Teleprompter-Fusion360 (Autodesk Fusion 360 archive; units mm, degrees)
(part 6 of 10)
sketch "Skizze70" plane through (0, 0, 150.455) normal (0, 0, 1) x axis (-1, 0, 0)
  line L1 (-222.0031, -133.7) -> (-201.1146, -176.9513)
  line L2 (-272.0031, -133.7) -> (-222.0031, -133.7)
  line L3 (-225.1361, -216.1858) -> (-272.0031, -133.7)
  line L4 (-222.0031, -323.7) -> (-222.0031, -228.0421)
  line L5 (-137.0031, -323.7) -> (-222.0031, -323.7)
  line L6 (-137.0031, -228.0421) -> (-137.0031, -323.7)
  line L7 (-87.0031, -133.7) -> (-133.87, -216.1858)
  line L8 (-137.0031, -133.7) -> (-87.0031, -133.7)
  line L9 (-157.8915, -176.9513) -> (-137.0031, -133.7)
  line L10 (-179.5031, -166.5139) -> (-179.5031, -323.7)
  arc A1 centre (-179.5031, -166.5139) radius 24 clockwise from (-157.8915, -176.9513) to (-201.1146, -176.9513)
  arc A2 centre (-246.0031, -228.0421) radius 24 clockwise from (-225.1361, -216.1858) to (-222.0031, -228.0421)
  arc A3 centre (-113.0031, -228.0421) radius 24 clockwise from (-137.0031, -228.0421) to (-133.87, -216.1858)
  circle C1 centre (-179.5031, -203.0903) radius 3.25
  circle C2 centre (-179.5031, -215.0903) radius 3.25
  circle C3 centre (-179.5031, -227.0903) radius 3.25
  circle C4 centre (-179.5031, -239.0903) radius 3.25
  circle C5 centre (-179.5031, -251.0903) radius 3.25
  circle C6 centre (-179.5031, -263.0903) radius 3.25
  circle C7 centre (-179.5031, -275.0903) radius 3.25
  circle C8 centre (-179.5031, -287.0903) radius 3.25
  circle C9 centre (-179.5031, -299.0903) radius 3.25
  point P17 (-179.5031, -323.7)
  point P4 (-179.5031, -166.5139)
  point P18 (-179.5031, -166.5139)
  point P19 (-179.5031, -203.0903)
  midpoint L5 P17
  coincident P4 P18
  coincident L10 P19
  dimension "d401" diameter C1 = 6.5
  dimension "d404" R-Pattern1-uDistance = -12
  dimension "d405" R-Pattern1-vDistance = 0
extrude "Extrusion71" cut sketch "Skizze70" profile of C1 C2 C3 C4 C5 C6 C7 C8 C9 against normal blind 20
extrude "Extrusion72" cut of existing geometry to an object
sketch "Skizze71" plane through (0, 0, 138.455) normal (0, 0, -1) x axis (1, 0, 0)
  line L1 (137.0031, -133.7) -> (157.8915, -176.9513)
  line L2 (87.0031, -133.7) -> (137.0031, -133.7)
  line L3 (133.87, -216.1858) -> (87.0031, -133.7)
  line L4 (137.0031, -323.7) -> (137.0031, -228.0421)
  line L5 (222.0031, -323.7) -> (137.0031, -323.7)
  line L6 (222.0031, -228.0421) -> (222.0031, -323.7)
  line L7 (272.0031, -133.7) -> (225.1361, -216.1858)
  line L8 (222.0031, -133.7) -> (272.0031, -133.7)
  line L9 (201.1146, -176.9513) -> (222.0031, -133.7)
  line L10 (164.5031, -299.0903) -> (164.5031, -203.0903)
  line L11 (194.5031, -203.0903) -> (194.5031, -299.0903)
  line L12 (179.5031, -299.0903) -> (179.5031, -203.0903)
  line L13 (137.0031, -311.6994) -> (222.0031, -311.6994)
  circle C1 centre (179.5031, -275.0903) radius 3.25
  circle C2 centre (179.5031, -227.0903) radius 3.25
  circle C3 centre (179.5031, -215.0903) radius 3.25
  circle C4 centre (179.5031, -263.0903) radius 3.25
  circle C5 centre (179.5031, -287.0903) radius 3.25
  circle C6 centre (179.5031, -239.0903) radius 3.25
  circle C7 centre (179.5031, -203.0903) radius 3.25
  circle C8 centre (179.5031, -251.0903) radius 3.25
  circle C9 centre (179.5031, -299.0903) radius 3.25
  arc A1 centre (113.0031, -228.0421) radius 24 clockwise from (133.87, -216.1858) to (137.0031, -228.0421)
  arc A2 centre (246.0031, -228.0421) radius 24 clockwise from (222.0031, -228.0421) to (225.1361, -216.1858)
  arc A3 centre (179.5031, -166.5139) radius 24 clockwise from (201.1146, -176.9513) to (157.8915, -176.9513)
  arc A4 centre (179.5031, -299.0903) radius 15 clockwise from (194.5031, -299.0903) to (164.5031, -299.0903)
  arc A5 centre (179.5031, -203.0903) radius 15 clockwise from (164.5031, -203.0903) to (194.5031, -203.0903)
  point P10 (179.5031, -299.0903)
  point P31 (179.5031, -299.0903)
  point P8 (179.5031, -203.0903)
  point P30 (179.5031, -203.0903)
  tangent L10 A4
  tangent A4 L11
  parallel L10 L11
  tangent L11 A5
  tangent L10 A5
  coincident P10 P31
  vertical L12
  coincident P8 P30
  dimension "d410" diameter A4 = 30
extrude "Extrusion73" cut sketch "Skizze71" profile of C1 C2 C3 C4 C5 C6 C7 C8 C9 A3 L10 A4 L11 A5 L13 against normal blind 8
sketch "Skizze72" plane through (0, 323.7, 0) normal (0, 1, 0) x axis (-1, 0, 0)
  line L1 (-137.0031, 0) -> (-222.0031, 0)
  line L2 (-137.0031, 138.455) -> (-137.0031, 0)
  line L3 (-222.0031, 138.455) -> (-137.0031, 138.455)
  line L4 (-222.0031, 0) -> (-222.0031, 138.455)
  line L5 (-137.0031, 150.455) -> (-137.0031, 138.455)
  line L6 (-222.0031, 150.455) -> (-137.0031, 150.455)
  line L7 (-222.0031, 138.455) -> (-222.0031, 150.455)
  line L8 (-137.0031, 138.455) -> (-222.0031, 138.455)
  line L9 (-154.0031, 138.455) -> (-154.0031, 150.455)
  line L10 (-171.0031, 138.455) -> (-171.0031, 150.455)
  line L11 (-188.0031, 138.455) -> (-188.0031, 150.455)
  line L12 (-205.0031, 138.455) -> (-205.0031, 150.455)
  point P10 (-154.0031, 150.455)
  point P11 (-154.0031, 138.455)
  point P12 (-171.0031, 150.455)
  point P13 (-171.0031, 138.455)
  point P14 (-188.0031, 150.455)
  point P15 (-188.0031, 138.455)
  point P16 (-205.0031, 150.455)
  point P17 (-205.0031, 138.455)
  coincident L6 P10
  coincident L8 P11
  perpendicular L8 L9
  coincident L6 P12
  coincident L8 P13
  perpendicular L8 L10
  coincident L6 P14
  coincident L3 P15
  perpendicular L3 L11
  coincident L6 P16
  coincident L8 P17
  perpendicular L8 L12
  dimension "d413" distance L5 L7 = 85
  dimension "d414" distance L5 L9 = 17 (= "85.00 mm / 5")
  dimension "d415" distance L9 L10 = 17 (= "d414")
  dimension "d416" distance L10 L11 = 17 (= "d414")
  dimension "d417" distance L11 L12 = 17 (= "d414")
extrude "Extrusion74" add sketch "Skizze72" profile of L3 L6 L8 L9 L10 L11 L12 against normal blind 12
sketch "Skizze73" plane through (0, 0, 150.455) normal (0, 0, 1) x axis (-1, 0, 0)
  line L1 (-222.0031, -133.7) -> (-201.1146, -176.9513)
  line L2 (-272.0031, -133.7) -> (-222.0031, -133.7)
  line L3 (-225.1361, -216.1858) -> (-272.0031, -133.7)
  line L4 (-222.0031, -323.7) -> (-222.0031, -228.0421)
  line L5 (-137.0031, -323.7) -> (-222.0031, -323.7)
  line L6 (-137.0031, -228.0421) -> (-137.0031, -323.7)
  line L7 (-87.0031, -133.7) -> (-133.87, -216.1858)
  line L8 (-137.0031, -133.7) -> (-87.0031, -133.7)
  line L9 (-157.8915, -176.9513) -> (-137.0031, -133.7)
  line L10 (-154.0031, -323.7) -> (-171.0031, -323.7)
  line L11 (-154.0031, -311.7) -> (-154.0031, -323.7)
  line L12 (-171.0031, -311.7) -> (-154.0031, -311.7)
  line L13 (-171.0031, -323.7) -> (-171.0031, -311.7)
  line L14 (-188.0031, -323.7) -> (-205.0031, -323.7)
  line L15 (-188.0031, -311.7) -> (-188.0031, -323.7)
  line L16 (-205.0031, -311.7) -> (-188.0031, -311.7)
  line L17 (-205.0031, -323.7) -> (-205.0031, -311.7)
  circle C1 centre (-179.5031, -275.0903) radius 3.25
  circle C2 centre (-179.5031, -227.0903) radius 3.25
  circle C3 centre (-179.5031, -215.0903) radius 3.25
  circle C4 centre (-179.5031, -263.0903) radius 3.25
  circle C5 centre (-179.5031, -287.0903) radius 3.25
  circle C6 centre (-179.5031, -239.0903) radius 3.25
  circle C7 centre (-179.5031, -203.0903) radius 3.25
  circle C8 centre (-179.5031, -251.0903) radius 3.25
  circle C9 centre (-179.5031, -299.0903) radius 3.25
  arc A1 centre (-179.5031, -166.5139) radius 24 clockwise from (-157.8915, -176.9513) to (-201.1146, -176.9513)
  arc A2 centre (-246.0031, -228.0421) radius 24 clockwise from (-225.1361, -216.1858) to (-222.0031, -228.0421)
  arc A3 centre (-113.0031, -228.0421) radius 24 clockwise from (-137.0031, -228.0421) to (-133.87, -216.1858)
extrude "Extrusion75" cut sketch "Skizze73" profile of L5 L10 L11 L12 L13 L14 L15 L16 L17 against normal blind 15
sketch "Skizze74" plane through (0, 0, 12) normal (0, 0, 1) x axis (-1, 0, 0)
  line L1 (-374.0031, -240.1877) -> (-366.2457, -240.1877)
  line L2 (-374.0031, -255.3404) -> (-374.0031, -240.1877)
  line L3 (-246.0031, -255.3404) -> (-374.0031, -255.3404)
  line L4 (-222.0031, -311.6994) -> (-222.0031, -279.3404)
  line L5 (-137.0031, -279.3404) -> (-137.0031, -311.6994)
  line L6 (14.9969, -255.3404) -> (-113.0031, -255.3404)
  line L7 (14.9969, -240.1877) -> (14.9969, -255.3404)
  line L8 (7.2396, -240.1877) -> (14.9969, -240.1877)
  line L9 (-362.0031, -240.1877) -> (2.9969, -240.1877)
  line L10 (-171.0031, -311.7) -> (-171.0031, -323.7)
  line L11 (-154.0031, -311.7) -> (-171.0031, -311.7)
  line L12 (-154.0031, -323.7) -> (-154.0031, -311.7)
  line L13 (-137.0031, -323.7) -> (-154.0031, -323.7)
  line L14 (-137.0031, -228.0421) -> (-137.0031, -323.7)
  line L15 (-87.0031, -133.7) -> (-133.87, -216.1858)
  line L16 (-137.0031, -133.7) -> (-87.0031, -133.7)
  line L17 (-157.8915, -176.9513) -> (-137.0031, -133.7)
  line L18 (-222.0031, -133.7) -> (-201.1146, -176.9513)
  line L19 (-272.0031, -133.7) -> (-222.0031, -133.7)
  line L20 (-225.1361, -216.1858) -> (-272.0031, -133.7)
  line L21 (-222.0031, -323.7) -> (-222.0031, -228.0421)
  line L22 (-205.0031, -323.7) -> (-222.0031, -323.7)
  line L23 (-205.0031, -311.7) -> (-205.0031, -323.7)
  line L24 (-188.0031, -311.7) -> (-205.0031, -311.7)
  line L25 (-188.0031, -323.7) -> (-188.0031, -311.7)
  line L26 (-171.0031, -323.7) -> (-188.0031, -323.7)
  circle C1 centre (8.9969, -246.1877) radius 1.5
  circle C2 centre (-368.0031, -246.1877) radius 1.5
  arc A1 centre (-364.1244, -238.0664) radius 3 clockwise from (-362.0031, -240.1877) to (-366.2457, -240.1877)
  arc A2 centre (-246.0031, -279.3404) radius 24 clockwise from (-246.0031, -255.3404) to (-222.0031, -279.3404)
  arc A3 centre (-113.0031, -279.3404) radius 24 clockwise from (-137.0031, -279.3404) to (-113.0031, -255.3404)
  arc A4 centre (5.1183, -238.0664) radius 3 clockwise from (7.2396, -240.1877) to (2.9969, -240.1877)
  arc A5 centre (-113.0031, -228.0421) radius 24 clockwise from (-137.0031, -228.0421) to (-133.87, -216.1858)
  arc A6 centre (-179.5031, -166.5139) radius 24 clockwise from (-157.8915, -176.9513) to (-201.1146, -176.9513)
  arc A7 centre (-246.0031, -228.0421) radius 24 clockwise from (-225.1361, -216.1858) to (-222.0031, -228.0421)
  circle C3 centre (-179.5031, -299.0903) radius 3.25
  circle C4 centre (-179.5031, -251.0903) radius 3.25
  circle C5 centre (-179.5031, -203.0903) radius 3.25
  circle C6 centre (-179.5031, -239.0903) radius 3.25
  circle C7 centre (-179.5031, -287.0903) radius 3.25
  circle C8 centre (-179.5031, -263.0903) radius 3.25
  circle C9 centre (-179.5031, -215.0903) radius 3.25
  circle C10 centre (-179.5031, -227.0903) radius 3.25
  circle C11 centre (-179.5031, -275.0903) radius 3.25
extrude "Extrusion76" add sketch "Skizze74" profile of L4 L5 L9 L10 L11 L12 L13 L14 L21 L22 L23 L24 L25 L26 C3 C4 C6 C7 C8 C11 against normal blind 12
sketch "Skizze76" plane through (0, 133.7, 0) normal (0, -1, 0) x axis (1, 0, 0)
  line L1 (272.0031, 150.455) -> (272.0031, 138.455)
  line L2 (222.0031, 150.455) -> (272.0031, 150.455)
  line L3 (222.0031, 138.455) -> (222.0031, 150.455)
  line L4 (272.0031, 138.455) -> (222.0031, 138.455)
  line L5 (247.0031, 138.455) -> (247.0031, 150.455)
  point P6 (247.0031, 150.455)
  point P7 (247.0031, 138.455)
  midpoint L2 P6
  midpoint L4 P7
extrude "Extrusion77" cut sketch "Skizze76" profile of L1 L2 L4 L5 along normal blind 12
sketch "Skizze77" plane through (0, 133.7, 0) normal (0, -1, 0) x axis (1, 0, 0)
  line L1 (272.0031, 150.455) -> (272.0031, 138.455)
  line L2 (222.0031, 150.455) -> (272.0031, 150.455)
  line L3 (222.0031, 138.455) -> (222.0031, 150.455)
  line L4 (272.0031, 138.455) -> (222.0031, 138.455)
  line L5 (247.0031, 150.455) -> (247.0031, 138.455)
  line L6 (272.0031, 150.455) -> (247.0031, 150.455)
  line L7 (272.0031, 232.955) -> (272.0031, 150.455)
  line L8 (111.0031, 256.955) -> (248.0031, 256.955)
  line L9 (87.0031, 138.455) -> (87.0031, 232.955)
  line L10 (137.0031, 138.455) -> (87.0031, 138.455)
  line L11 (137.0031, 202.455) -> (137.0031, 138.455)
  line L12 (192.0031, 232.455) -> (167.0031, 232.455)
  line L13 (222.0031, 138.455) -> (222.0031, 202.455)
  line L14 (247.0031, 138.455) -> (222.0031, 138.455)
  circle C1 centre (112.0031, 191.955) radius 2
  circle C2 centre (112.0031, 231.955) radius 2
  circle C3 centre (247.0031, 231.955) radius 2
  circle C4 centre (247.0031, 191.955) radius 2
  arc A1 centre (248.0031, 232.955) radius 24 clockwise from (248.0031, 256.955) to (272.0031, 232.955)
  arc A2 centre (111.0031, 232.955) radius 24 clockwise from (87.0031, 232.955) to (111.0031, 256.955)
  arc A3 centre (167.0031, 202.455) radius 30 clockwise from (137.0031, 202.455) to (167.0031, 232.455)
  arc A4 centre (192.0031, 202.455) radius 30 clockwise from (192.0031, 232.455) to (222.0031, 202.455)
extrude "Extrusion78" add sketch "Skizze77" profile of L1 L2 L4 L5 L6 along normal blind 12
sketch "Skizze78" plane through (0, 121.7, 0) normal (0, -1, 0) x axis (1, 0, 0)
  line L1 (247.0031, 150.455) -> (247.0031, 138.455)
  line L2 (272.0031, 150.455) -> (247.0031, 150.455)
  line L3 (272.0031, 232.955) -> (272.0031, 150.455)
  line L4 (111.0031, 256.955) -> (248.0031, 256.955)
  line L5 (87.0031, 138.455) -> (87.0031, 232.955)
  line L6 (137.0031, 138.455) -> (87.0031, 138.455)
  line L7 (137.0031, 202.455) -> (137.0031, 138.455)
  line L8 (192.0031, 232.455) -> (167.0031, 232.455)
  line L9 (222.0031, 138.455) -> (222.0031, 202.455)
  line L10 (247.0031, 138.455) -> (222.0031, 138.455)
  line L11 (137.0031, 163.3013) -> (137.0031, 150.455)
  line L12 (137.0031, 202.455) -> (137.0031, 189.1087)
  line L13 (192.0031, 232.455) -> (167.0031, 232.455)
  line L14 (222.0031, 189.1083) -> (222.0031, 202.455)
  line L15 (222.0031, 150.455) -> (222.0031, 163.3017)
  line L16 (374.0031, 150.455) -> (222.0031, 150.455)
  line L17 (374.0031, 181.955) -> (374.0031, 150.455)
  line L18 (366.2457, 181.955) -> (374.0031, 181.955)
  line L19 (362.0031, 209.2124) -> (362.0031, 186.1976)
  line L20 (374.0031, 213.455) -> (366.2457, 213.455)
  line L21 (374.0031, 244.955) -> (374.0031, 213.455)
  line L22 (366.2457, 244.955) -> (374.0031, 244.955)
  line L23 (362.0031, 256.955) -> (362.0031, 249.1976)
  line L24 (-2.9969, 256.955) -> (362.0031, 256.955)
  line L25 (-2.9969, 249.1976) -> (-2.9969, 256.955)
  line L26 (-14.9969, 244.955) -> (-7.2396, 244.955)
  line L27 (-14.9969, 213.455) -> (-14.9969, 244.955)
  line L28 (-7.2396, 213.455) -> (-14.9969, 213.455)
  line L29 (-2.9969, 186.1976) -> (-2.9969, 209.2124)
  line L30 (-14.9969, 181.955) -> (-7.2396, 181.955)
  line L31 (-14.9969, 150.455) -> (-14.9969, 181.955)
  line L32 (137.0031, 150.455) -> (-14.9969, 150.455)
  line L33 (112.0031, 150.455) -> (112.0031, 138.455)
  circle C1 centre (112.0031, 191.955) radius 2
  circle C2 centre (112.0031, 231.955) radius 2
  circle C3 centre (247.0031, 231.955) radius 2
  circle C4 centre (247.0031, 191.955) radius 2
  arc A1 centre (248.0031, 232.955) radius 24 clockwise from (248.0031, 256.955) to (272.0031, 232.955)
  arc A2 centre (111.0031, 232.955) radius 24 clockwise from (87.0031, 232.955) to (111.0031, 256.955)
  arc A3 centre (167.0031, 202.455) radius 30 clockwise from (137.0031, 202.455) to (167.0031, 232.455)
  arc A4 centre (192.0031, 202.455) radius 30 clockwise from (192.0031, 232.455) to (222.0031, 202.455)
  circle C5 centre (247.0031, 191.955) radius 2
  circle C6 centre (112.0031, 191.955) radius 2
  circle C7 centre (247.0031, 231.955) radius 2
  circle C8 centre (112.0031, 231.955) radius 2
  arc A5 centre (141.7525, 176.205) radius 13.75 clockwise from (137.0031, 163.3013) to (137.0031, 189.1087)
  arc A6 centre (167.0031, 202.455) radius 30 clockwise from (137.0031, 202.455) to (167.0031, 232.455)
  arc A7 centre (192.0031, 202.455) radius 30 clockwise from (192.0031, 232.455) to (222.0031, 202.455)
  arc A8 centre (217.2525, 176.205) radius 13.75 clockwise from (222.0031, 189.1083) to (222.0031, 163.3017)
  arc A9 centre (364.1244, 184.0763) radius 3 clockwise from (366.2457, 181.955) to (362.0031, 186.1976)
  arc A10 centre (364.1244, 211.3337) radius 3 clockwise from (362.0031, 209.2124) to (366.2457, 213.455)
  arc A11 centre (364.1244, 247.0763) radius 3 clockwise from (366.2457, 244.955) to (362.0031, 249.1976)
  arc A12 centre (-5.1183, 247.0763) radius 3 clockwise from (-2.9969, 249.1976) to (-7.2396, 244.955)
  arc A13 centre (-5.1183, 211.3337) radius 3 clockwise from (-7.2396, 213.455) to (-2.9969, 209.2124)
  arc A14 centre (-5.1183, 184.0763) radius 3 clockwise from (-2.9969, 186.1976) to (-7.2396, 181.955)
  point P70 (112.0031, 138.455)
  point P71 (112.0031, 150.455)
  midpoint L6 P70
  coincident L32 P71
  perpendicular L32 L33
extrude "Extrusion79" cut sketch "Skizze78" profile of L5 L6 L32 L33 against normal blind 12
sketch "Skizze79" plane through (0, 133.7, 0) normal (0, -1, 0) x axis (1, 0, 0)
  line L1 (137.0031, 138.455) -> (87.0031, 138.455)
  line L2 (137.0031, 150.455) -> (137.0031, 138.455)
  line L3 (87.0031, 150.455) -> (137.0031, 150.455)
  line L4 (87.0031, 138.455) -> (87.0031, 150.455)
  line L5 (112.0031, 138.455) -> (112.0031, 150.455)
  line L6 (87.0031, 150.455) -> (112.0031, 150.455)
  line L7 (87.0031, 138.455) -> (87.0031, 150.455)
  line L8 (112.0031, 138.455) -> (87.0031, 138.455)
  line L9 (112.0031, 150.455) -> (112.0031, 138.455)
  point P2 (87.0031, 138.455)
  point P10 (87.0031, 138.455)
  point P6 (112.0031, 150.455)
  point P8 (112.0031, 150.455)
  horizontal L6
  vertical L7
  horizontal L8
  vertical L9
  coincident P2 P10
  coincident P6 P8
extrude "Extrusion80" add sketch "Skizze79" profile of L1 L3 L4 L5 L6 L7 L8 L9 along normal blind 12
chamfer "Fase1" distance 3
sketch "Skizze80" plane through (0, 121.7, 0) normal (0, -1, 0) x axis (1, 0, 0)
  line L1 (112.0031, 150.455) -> (87.0031, 150.455)
  line L2 (112.0031, 138.455) -> (112.0031, 150.455)
  line L3 (137.0031, 138.455) -> (112.0031, 138.455)
  line L4 (137.0031, 202.455) -> (137.0031, 138.455)
  line L5 (192.0031, 232.455) -> (167.0031, 232.455)
  line L6 (222.0031, 138.455) -> (222.0031, 202.455)
  line L7 (247.0031, 138.455) -> (222.0031, 138.455)
  line L8 (247.0031, 150.455) -> (247.0031, 138.455)
  line L9 (272.0031, 150.455) -> (247.0031, 150.455)
  line L10 (272.0031, 232.955) -> (272.0031, 150.455)
  line L11 (111.0031, 256.955) -> (248.0031, 256.955)
  line L12 (87.0031, 150.455) -> (87.0031, 232.955)
  line L13 (247.0031, 150.455) -> (112.0031, 150.455)
  line L14 (137.0031, 150.455) -> (112.0031, 138.455)
  line L15 (137.0031, 138.455) -> (112.0031, 150.455)
  line L16 (247.0031, 150.455) -> (222.0031, 138.455)
  line L17 (222.0031, 150.455) -> (247.0031, 138.455)
  arc A1 centre (167.0031, 202.455) radius 30 clockwise from (137.0031, 202.455) to (167.0031, 232.455)
  arc A2 centre (192.0031, 202.455) radius 30 clockwise from (192.0031, 232.455) to (222.0031, 202.455)
  arc A3 centre (248.0031, 232.955) radius 24 clockwise from (248.0031, 256.955) to (272.0031, 232.955)
  arc A4 centre (111.0031, 232.955) radius 24 clockwise from (87.0031, 232.955) to (111.0031, 256.955)
  circle C1 centre (247.0031, 191.955) radius 2
  circle C2 centre (247.0031, 231.955) radius 2
  circle C3 centre (112.0031, 231.955) radius 2
  circle C4 centre (112.0031, 191.955) radius 2
  circle C5 centre (124.5031, 144.455) radius 1.5
  circle C6 centre (234.5031, 144.455) radius 1.5
  point P3 (112.0031, 150.455)
  point P26 (112.0031, 150.455)
  point P14 (247.0031, 150.455)
  point P27 (247.0031, 150.455)
  point P4 (112.0031, 138.455)
  point P28 (112.0031, 138.455)
  point P29 (137.0031, 150.455)
  point P30 (112.0031, 150.455)
  point P5 (137.0031, 138.455)
  point P31 (137.0031, 138.455)
  point P12 (222.0031, 138.455)
  point P32 (222.0031, 138.455)
  point P33 (247.0031, 150.455)
  point P13 (247.0031, 138.455)
  point P34 (247.0031, 138.455)
  point P35 (222.0031, 150.455)
  point P36 (124.5031, 144.455)
  point P37 (234.5031, 144.455)
  point P38 (124.5031, 144.455)
  point P39 (234.5031, 144.455)
  coincident P3 P26
  coincident P14 P27
  coincident P4 P28
  coincident L4 P29
  coincident L13 P29
  coincident P3 P30
  coincident P5 P31
  coincident P12 P32
  coincident P14 P33
  coincident P13 P34
  coincident L6 P35
  coincident L13 P35
  midpoint L14 P36
  midpoint L17 P37
  coincident P36 P38
  coincident P37 P39
  dimension "d433" diameter C5 = 3
  dimension "d434" diameter C6 = 3
extrude "Extrusion81" cut sketch "Skizze80" profile of C5 C6 against normal blind 30
chamfer "Fase2" distance 3
sketch "Skizze81" plane through (0, 0, 138.455) normal (0, 0, -1) x axis (1, 0, 0)
  line L1 (154.0031, -311.7) -> (154.0031, -323.7)
  line L2 (171.0031, -311.7) -> (154.0031, -311.7)
  line L3 (171.0031, -323.7) -> (171.0031, -311.7)
  line L4 (188.0031, -323.7) -> (171.0031, -323.7)
  line L5 (188.0031, -311.7) -> (188.0031, -323.7)
  line L6 (205.0031, -311.7) -> (188.0031, -311.7)
  line L7 (205.0031, -323.7) -> (205.0031, -311.7)
  line L8 (222.0031, -323.7) -> (205.0031, -323.7)
  line L9 (222.0031, -228.0421) -> (222.0031, -323.7)
  line L10 (272.0031, -133.7) -> (225.1361, -216.1858)
  line L11 (272.0031, -121.7) -> (272.0031, -133.7)
  line L12 (247.0031, -121.7) -> (272.0031, -121.7)
  line L13 (247.0031, -133.7) -> (247.0031, -121.7)
  line L14 (222.0031, -133.7) -> (247.0031, -133.7)
  line L15 (201.1146, -176.9513) -> (222.0031, -133.7)
  line L16 (194.5031, -299.0903) -> (194.5031, -203.0903)
  line L17 (171.3784, -311.6994) -> (187.6277, -311.6994)
  line L18 (164.5031, -203.0903) -> (164.5031, -299.0903)
  line L19 (137.0031, -133.7) -> (157.8915, -176.9513)
  line L20 (112.0031, -133.7) -> (137.0031, -133.7)
  line L21 (112.0031, -121.7) -> (112.0031, -133.7)
  line L22 (87.0031, -121.7) -> (112.0031, -121.7)
  line L23 (87.0031, -133.7) -> (87.0031, -121.7)
  line L24 (133.87, -216.1858) -> (87.0031, -133.7)
  line L25 (137.0031, -323.7) -> (137.0031, -228.0421)
  line L26 (154.0031, -323.7) -> (137.0031, -323.7)
  line L27 (272.0031, -133.7) -> (87.0031, -133.7)
  line L28 (247.0031, -121.7) -> (272.0031, -133.7)
  line L29 (272.0031, -121.7) -> (247.0031, -133.7)
  line L30 (112.0031, -121.7) -> (87.0031, -133.7)
  line L31 (112.0031, -133.7) -> (87.0031, -121.7)
  arc A1 centre (246.0031, -228.0421) radius 24 clockwise from (222.0031, -228.0421) to (225.1361, -216.1858)
  arc A2 centre (179.5031, -166.5139) radius 24 clockwise from (201.1146, -176.9513) to (186.062, -189.6003)
  arc A3 centre (179.5031, -203.0903) radius 15 clockwise from (186.062, -189.6003) to (194.5031, -203.0903)
  arc A4 centre (179.5031, -299.0903) radius 15 clockwise from (194.5031, -299.0903) to (187.6277, -311.6994)
  arc A5 centre (179.5031, -299.0903) radius 15 clockwise from (171.3784, -311.6994) to (164.5031, -299.0903)
  arc A6 centre (179.5031, -203.0903) radius 15 clockwise from (164.5031, -203.0903) to (172.9441, -189.6003)
  arc A7 centre (179.5031, -166.5139) radius 24 clockwise from (172.9441, -189.6003) to (157.8915, -176.9513)
  arc A8 centre (113.0031, -228.0421) radius 24 clockwise from (133.87, -216.1858) to (137.0031, -228.0421)
  circle C1 centre (99.5031, -127.7) radius 1.5
  circle C2 centre (259.5031, -127.7) radius 1.5
  point P36 (87.0031, -133.7)
  point P41 (87.0031, -133.7)
  point P14 (272.0031, -133.7)
  point P42 (272.0031, -133.7)
  point P43 (272.0031, -133.7)
  point P16 (247.0031, -121.7)
  point P44 (247.0031, -121.7)
  point P17 (247.0031, -133.7)
  point P45 (247.0031, -133.7)
  point P15 (272.0031, -121.7)
  point P46 (272.0031, -121.7)
  point P47 (87.0031, -133.7)
  point P34 (112.0031, -121.7)
  point P48 (112.0031, -121.7)
  point P35 (87.0031, -121.7)
  point P49 (87.0031, -121.7)
  point P33 (112.0031, -133.7)
  point P50 (112.0031, -133.7)
  point P51 (99.5031, -127.7)
  point P52 (259.5031, -127.7)
  point P53 (99.5031, -127.7)
  point P54 (259.5031, -127.7)
  coincident P36 P41
  coincident P14 P42
  coincident P14 P43
  coincident P16 P44
  coincident P17 P45
  coincident P15 P46
  coincident P36 P47
  coincident P34 P48
  coincident P35 P49
  coincident P33 P50
  midpoint L31 P51
  midpoint L29 P52
  coincident P51 P53
  coincident P52 P54
  dimension "d438" diameter C1 = 3
  dimension "d439" diameter C2 = 3
extrude "Extrusion82" cut sketch "Skizze81" profile of C1 C2 against normal blind 35
chamfer "Fase3" distance 3
sketch "Skizze82" plane through (0, 0, 150.455) normal (0, 0, 1) x axis (-1, 0, 0)
  line L1 (-171.0031, -311.7) -> (-171.0031, -323.7)
  line L2 (-154.0031, -311.7) -> (-171.0031, -311.7)
  line L3 (-154.0031, -323.7) -> (-154.0031, -311.7)
  line L4 (-137.0031, -323.7) -> (-154.0031, -323.7)
  line L5 (-137.0031, -228.0421) -> (-137.0031, -323.7)
  line L6 (-87.0031, -133.7) -> (-133.87, -216.1858)
  line L7 (-87.0031, -121.7) -> (-87.0031, -133.7)
  line L8 (-112.0031, -121.7) -> (-87.0031, -121.7)
  line L9 (-112.0031, -133.7) -> (-112.0031, -121.7)
  line L10 (-137.0031, -133.7) -> (-112.0031, -133.7)
  line L11 (-157.8915, -176.9513) -> (-137.0031, -133.7)
  line L12 (-222.0031, -133.7) -> (-201.1146, -176.9513)
  line L13 (-247.0031, -133.7) -> (-222.0031, -133.7)
  line L14 (-247.0031, -121.7) -> (-247.0031, -133.7)
  line L15 (-272.0031, -121.7) -> (-247.0031, -121.7)
  line L16 (-272.0031, -133.7) -> (-272.0031, -121.7)
  line L17 (-225.1361, -216.1858) -> (-272.0031, -133.7)
  line L18 (-222.0031, -323.7) -> (-222.0031, -228.0421)
  line L19 (-205.0031, -323.7) -> (-222.0031, -323.7)
  line L20 (-205.0031, -311.7) -> (-205.0031, -323.7)
  line L21 (-188.0031, -311.7) -> (-205.0031, -311.7)
  line L22 (-188.0031, -323.7) -> (-188.0031, -311.7)
  line L23 (-171.0031, -323.7) -> (-188.0031, -323.7)
  line L24 (-137.0031, -311.7) -> (-222.0031, -311.7)
  line L25 (-154.0031, -323.7) -> (-137.0031, -311.7)
  line L26 (-137.0031, -323.7) -> (-154.0031, -311.7)
  line L27 (-188.0031, -323.7) -> (-171.0031, -311.7)
  line L28 (-171.0031, -323.7) -> (-188.0031, -311.7)
  line L29 (-222.0031, -323.7) -> (-205.0031, -311.7)
  line L30 (-205.0031, -323.7) -> (-222.0031, -311.7)
  circle C1 centre (-99.5031, -127.7) radius 1.5
  circle C2 centre (-259.5031, -127.7) radius 1.5
  arc A1 centre (-113.0031, -228.0421) radius 24 clockwise from (-137.0031, -228.0421) to (-133.87, -216.1858)
  arc A2 centre (-179.5031, -166.5139) radius 24 clockwise from (-157.8915, -176.9513) to (-201.1146, -176.9513)
  arc A3 centre (-246.0031, -228.0421) radius 24 clockwise from (-225.1361, -216.1858) to (-222.0031, -228.0421)
  circle C3 centre (-179.5031, -299.0903) radius 3.25
  circle C4 centre (-179.5031, -251.0903) radius 3.25
  circle C5 centre (-179.5031, -203.0903) radius 3.25
  circle C6 centre (-179.5031, -239.0903) radius 3.25
  circle C7 centre (-179.5031, -287.0903) radius 3.25
  circle C8 centre (-179.5031, -263.0903) radius 3.25
  circle C9 centre (-179.5031, -215.0903) radius 3.25
  circle C10 centre (-179.5031, -227.0903) radius 3.25
  circle C11 centre (-179.5031, -275.0903) radius 3.25
  circle C12 centre (-145.5031, -317.7) radius 1.5
  circle C13 centre (-213.5031, -317.7) radius 1.5
  circle C14 centre (-179.5031, -317.7) radius 1.5
  point P42 (-222.0031, -311.7)
  point P43 (-137.0031, -311.7)
  point P7 (-154.0031, -323.7)
  point P44 (-154.0031, -323.7)
  point P6 (-154.0031, -311.7)
  point P45 (-154.0031, -311.7)
  point P8 (-137.0031, -323.7)
  point P46 (-137.0031, -323.7)
  point P5 (-171.0031, -311.7)
  point P47 (-171.0031, -311.7)
  point P32 (-188.0031, -323.7)
  point P48 (-188.0031, -323.7)
  point P31 (-188.0031, -311.7)
  point P49 (-188.0031, -311.7)
  point P4 (-171.0031, -323.7)
  point P50 (-171.0031, -323.7)
  point P30 (-205.0031, -311.7)
  point P51 (-205.0031, -311.7)
  point P28 (-222.0031, -323.7)
  point P52 (-222.0031, -323.7)
  point P29 (-205.0031, -323.7)
  point P53 (-205.0031, -323.7)
  point P54 (-145.5031, -317.7)
  point P55 (-213.5031, -317.7)
  point P56 (-179.5031, -317.7)
  coincident L18 P42
  coincident L5 P43
  perpendicular L5 L24
  coincident P7 P44
  coincident P6 P45
  coincident P8 P46
  coincident P5 P47
  coincident P32 P48
  coincident P31 P49
  coincident P4 P50
  coincident P30 P51
  coincident P28 P52
  coincident P29 P53
  parallel L28 L30
  midpoint L26 P54
  midpoint L30 P55
  midpoint L27 P56
  dimension "d443" diameter C12 = 3
  dimension "d444" diameter C13 = 3
  dimension "d445" diameter C14 = 3
extrude "Extrusion83" cut sketch "Skizze82" profile of C12 C13 C14 against normal blind 16
chamfer "Fase4" distance 3
sketch "Skizze83" plane through (0, 0, 150.455) normal (0, 0, 1) x axis (-1, 0, 0)
  line L1 (-171.0031, -311.7) -> (-171.0031, -323.7)
  line L2 (-154.0031, -311.7) -> (-171.0031, -311.7)
  line L3 (-154.0031, -323.7) -> (-154.0031, -311.7)
  line L4 (-137.0031, -323.7) -> (-154.0031, -323.7)
  line L5 (-137.0031, -228.0421) -> (-137.0031, -323.7)
  line L6 (-87.0031, -133.7) -> (-133.87, -216.1858)
  line L7 (-87.0031, -121.7) -> (-87.0031, -133.7)
  line L8 (-112.0031, -121.7) -> (-87.0031, -121.7)
  line L9 (-112.0031, -133.7) -> (-112.0031, -121.7)
  line L10 (-137.0031, -133.7) -> (-112.0031, -133.7)
  line L11 (-157.8915, -176.9513) -> (-137.0031, -133.7)
  line L12 (-222.0031, -133.7) -> (-201.1146, -176.9513)
  line L13 (-247.0031, -133.7) -> (-222.0031, -133.7)
  line L14 (-247.0031, -121.7) -> (-247.0031, -133.7)
  line L15 (-272.0031, -121.7) -> (-247.0031, -121.7)
  line L16 (-272.0031, -133.7) -> (-272.0031, -121.7)
  line L17 (-225.1361, -216.1858) -> (-272.0031, -133.7)
  line L18 (-222.0031, -323.7) -> (-222.0031, -228.0421)
  line L19 (-205.0031, -323.7) -> (-222.0031, -323.7)
  line L20 (-205.0031, -311.7) -> (-205.0031, -323.7)
  line L21 (-188.0031, -311.7) -> (-205.0031, -311.7)
  line L22 (-188.0031, -323.7) -> (-188.0031, -311.7)
  line L23 (-171.0031, -323.7) -> (-188.0031, -323.7)
  line L24 (-116.3694, -129.3337) -> (-112.0031, -133.7)
  line L25 (-105.8281, -133.7) -> (-112.0031, -133.7)
  line L26 (-238.2978, -124.9947) -> (-247.0031, -133.7)
  line L27 (-234.6919, -133.7) -> (-247.0031, -133.7)
  line L28 (-162.105, -319.8019) -> (-154.0031, -311.7)
  line L29 (-142.5452, -311.7) -> (-154.0031, -311.7)
  line L30 (-164.9194, -317.7836) -> (-171.0031, -311.7)
  line L31 (-162.3995, -311.7) -> (-171.0031, -311.7)
  line L32 (-196.0439, -319.7408) -> (-188.0031, -311.7)
  line L33 (-176.6316, -311.7) -> (-188.0031, -311.7)
  line L34 (-191.7805, -324.9226) -> (-205.0031, -311.7)
  line L35 (-186.3035, -311.7) -> (-205.0031, -311.7)
  circle C1 centre (-179.5031, -317.7) radius 4.5
  circle C2 centre (-179.5031, -275.0903) radius 3.25
  circle C3 centre (-179.5031, -227.0903) radius 3.25
  circle C4 centre (-179.5031, -215.0903) radius 3.25
  circle C5 centre (-179.5031, -263.0903) radius 3.25
  circle C6 centre (-179.5031, -287.0903) radius 3.25
  circle C7 centre (-179.5031, -239.0903) radius 3.25
  circle C8 centre (-179.5031, -203.0903) radius 3.25
  circle C9 centre (-179.5031, -251.0903) radius 3.25
  circle C10 centre (-179.5031, -299.0903) radius 3.25
  arc A1 centre (-113.0031, -228.0421) radius 24 clockwise from (-137.0031, -228.0421) to (-133.87, -216.1858)
  arc A2 centre (-179.5031, -166.5139) radius 24 clockwise from (-157.8915, -176.9513) to (-201.1146, -176.9513)
  arc A3 centre (-246.0031, -228.0421) radius 24 clockwise from (-225.1361, -216.1858) to (-222.0031, -228.0421)
  circle C11 centre (-259.5031, -127.7) radius 1.5
  circle C12 centre (-99.5031, -127.7) radius 1.5
  circle C13 centre (-213.5031, -317.7) radius 4.5
  circle C14 centre (-145.5031, -317.7) radius 4.5
  circle C15 centre (-114.1597, -131.5433) radius 3.05
  circle C16 centre (-244.8464, -131.5433) radius 3.05
  circle C17 centre (-156.1597, -313.8567) radius 3.05
  circle C18 centre (-168.8464, -313.8567) radius 3.05
  circle C19 centre (-202.8464, -313.8567) radius 3.05
  circle C20 centre (-190.1597, -313.8567) radius 3.05
  point P23 (-112.0031, -133.7)
  point P45 (-112.0031, -133.7)
  point P48 (-114.1597, -131.5433)
  point P29 (-247.0031, -133.7)
  point P49 (-247.0031, -133.7)
  point P52 (-244.8464, -131.5433)
  point P14 (-154.0031, -311.7)
  point P53 (-154.0031, -311.7)
  point P13 (-171.0031, -311.7)
  point P56 (-171.0031, -311.7)
  point P39 (-188.0031, -311.7)
  point P59 (-188.0031, -311.7)
  point P38 (-205.0031, -311.7)
  point P62 (-205.0031, -311.7)
  point P65 (-156.1597, -313.8567)
  point P66 (-168.8464, -313.8567)
  point P67 (-202.8464, -313.8567)
  point P68 (-190.1597, -313.8567)
  horizontal L25
  coincident P23 P45
  coincident L24 P48
  horizontal L27
  coincident P29 P49
  coincident L26 P52
  horizontal L29
  coincident P14 P53
  horizontal L31
  coincident P13 P56
  horizontal L33
  coincident P39 P59
  horizontal L35
  coincident P38 P62
  coincident L28 P65
  coincident L30 P66
  coincident L34 P67
  coincident L32 P68
  dimension "d449" angle L24 L25 = 135
  dimension "d450" diameter C15 = 6.1
  dimension "d451" distance P45 P48 = 3.05 (= "( 6.1 / 2 ) * 1 mm")
  dimension "d452" angle L26 L27 = 45
  dimension "d453" diameter C16 = 6.1
  dimension "d454" distance P49 P52 = 3.05
  dimension "d455" angle L28 L29 = 135
  dimension "d456" angle L30 L31 = 45
  dimension "d457" angle L32 L33 = 135
  dimension "d458" angle L34 L35 = 45
  dimension "d459" diameter C17 = 6.1
  dimension "d460" diameter C18 = 6.1
  dimension "d461" diameter C19 = 6.1
  dimension "d462" diameter C20 = 6.1
  dimension "d463" distance P62 P67 = 3.05
  dimension "d464" distance P59 P68 = 3.05
  dimension "d465" distance P56 P66 = 3.05
  dimension "d466" distance P53 P65 = 3.05
extrude "Extrusion84" cut sketch "Skizze83" profile of L1 L2 L3 L9 L10 L13 L14 L20 L21 L22 C15 C16 C17 C18 C19 C20 against normal blind 30
sketch "Skizze84" plane through (0, 133.7, 0) normal (0, 1, 0) x axis (-1, 0, 0)
  line L1 (-87.0031, 150.455) -> (-112.0031, 150.455)
  line L2 (-87.0031, 232.955) -> (-87.0031, 150.455)
  line L3 (-248.0031, 256.955) -> (-111.0031, 256.955)
  line L4 (-272.0031, 150.455) -> (-272.0031, 232.955)
  line L5 (-247.0031, 150.455) -> (-272.0031, 150.455)
  line L6 (-247.0031, 138.455) -> (-247.0031, 150.455)
  line L7 (-222.0031, 138.455) -> (-247.0031, 138.455)
  line L8 (-222.0031, 202.455) -> (-222.0031, 138.455)
  line L9 (-167.0031, 232.455) -> (-192.0031, 232.455)
  line L10 (-137.0031, 138.455) -> (-137.0031, 202.455)
  line L11 (-112.0031, 138.455) -> (-137.0031, 138.455)
  line L12 (-112.0031, 150.455) -> (-112.0031, 138.455)
  line L13 (-256.514, 140.9441) -> (-247.0031, 150.455)
  line L14 (-233.5526, 150.455) -> (-247.0031, 150.455)
  line L15 (-104.8923, 143.3443) -> (-112.0031, 150.455)
  line L16 (-101.947, 150.455) -> (-112.0031, 150.455)
  circle C1 centre (-124.5031, 144.455) radius 1.5
  circle C2 centre (-234.5031, 144.455) radius 1.5
  circle C3 centre (-247.0031, 231.955) radius 5
  circle C4 centre (-112.0031, 231.955) radius 5
  arc A1 centre (-111.0031, 232.955) radius 24 clockwise from (-111.0031, 256.955) to (-87.0031, 232.955)
  arc A2 centre (-248.0031, 232.955) radius 24 clockwise from (-272.0031, 232.955) to (-248.0031, 256.955)
  arc A3 centre (-192.0031, 202.455) radius 30 clockwise from (-222.0031, 202.455) to (-192.0031, 232.455)
  arc A4 centre (-167.0031, 202.455) radius 30 clockwise from (-167.0031, 232.455) to (-137.0031, 202.455)
  circle C5 centre (-112.0031, 191.955) radius 5
  circle C6 centre (-247.0031, 191.955) radius 5
  circle C7 centre (-249.1597, 148.2983) radius 3.05
  circle C8 centre (-109.8464, 148.2983) radius 3.05
  point P15 (-247.0031, 150.455)
  point P28 (-247.0031, 150.455)
  point P6 (-112.0031, 150.455)
  point P31 (-112.0031, 150.455)
  point P34 (-249.1597, 148.2983)
  point P35 (-109.8464, 148.2983)
  horizontal L14
  coincident P15 P28
  horizontal L16
  coincident P6 P31
  coincident L13 P34
  coincident L15 P35
  dimension "d469" angle L13 L14 = 135
  dimension "d470" angle L15 L16 = 45
  dimension "d471" diameter C7 = 6.1
  dimension "d472" diameter C8 = 6.1
  dimension "d473" distance P31 P35 = 3.05
  dimension "d474" distance P28 P34 = 3.05
extrude "Extrusion85" cut sketch "Skizze84" profile of L1 L5 L6 L12 C7 C8 against normal blind 14
sketch "Skizze85" plane through (0, 323.7, 0) normal (0, 1, 0) x axis (-1, 0, 0)
  line L1 (-137.0031, 0) -> (-222.0031, 0)
  line L2 (-137.0031, 138.455) -> (-137.0031, 0)
  line L3 (-154.0031, 138.455) -> (-137.0031, 138.455)
  line L4 (-154.0031, 150.455) -> (-154.0031, 138.455)
  line L5 (-171.0031, 150.455) -> (-154.0031, 150.455)
  line L6 (-171.0031, 138.455) -> (-171.0031, 150.455)
  line L7 (-188.0031, 138.455) -> (-171.0031, 138.455)
  line L8 (-188.0031, 150.455) -> (-188.0031, 138.455)
  line L9 (-205.0031, 150.455) -> (-188.0031, 150.455)
  line L10 (-205.0031, 138.455) -> (-205.0031, 150.455)
  line L11 (-222.0031, 138.455) -> (-205.0031, 138.455)
  line L12 (-222.0031, 0) -> (-222.0031, 138.455)
  line L13 (-154.0031, 138.455) -> (-205.0031, 138.455)
  line L14 (-188.0031, 150.455) -> (-205.0031, 138.455)
  line L15 (-188.0031, 138.455) -> (-205.0031, 150.455)
  line L16 (-154.0031, 150.455) -> (-171.0031, 138.455)
  line L17 (-154.0031, 138.455) -> (-171.0031, 150.455)
  circle C1 centre (-196.5031, 144.455) radius 1.5
  circle C2 centre (-162.5031, 144.455) radius 1.5
  point P12 (-205.0031, 138.455)
  point P14 (-205.0031, 138.455)
  point P5 (-154.0031, 138.455)
  point P15 (-154.0031, 138.455)
  point P16 (-205.0031, 138.455)
  point P10 (-188.0031, 150.455)
  point P17 (-188.0031, 150.455)
  point P11 (-205.0031, 150.455)
  point P18 (-205.0031, 150.455)
  point P9 (-188.0031, 138.455)
  point P19 (-188.0031, 138.455)
  point P8 (-171.0031, 138.455)
  point P20 (-171.0031, 138.455)
  point P6 (-154.0031, 150.455)
  point P21 (-154.0031, 150.455)
  point P7 (-171.0031, 150.455)
  point P22 (-171.0031, 150.455)
  point P23 (-154.0031, 138.455)
  point P24 (-196.5031, 144.455)
  point P25 (-162.5031, 144.455)
  coincident P12 P14
  coincident P5 P15
  coincident P12 P16
  coincident P10 P17
  coincident P11 P18
  coincident P9 P19
  coincident P8 P20
  coincident P6 P21
  coincident P7 P22
  coincident P5 P23
  midpoint L14 P24
  midpoint L16 P25
  dimension "d477" diameter C1 = 3
  dimension "d478" diameter C2 = 3
extrude "Extrusion86" cut sketch "Skizze85" profile of C1 C2 against normal blind 14
sketch "Skizze86" plane through (0, 323.7, 0) normal (0, 1, 0) x axis (-1, 0, 0)
  line L1 (-137.0031, 0) -> (-222.0031, 0)
  line L2 (-137.0031, 138.455) -> (-137.0031, 0)
  line L3 (-154.0031, 138.455) -> (-137.0031, 138.455)
  line L4 (-154.0031, 150.455) -> (-154.0031, 138.455)
  line L5 (-171.0031, 150.455) -> (-154.0031, 150.455)
  line L6 (-171.0031, 138.455) -> (-171.0031, 150.455)
  line L7 (-188.0031, 138.455) -> (-171.0031, 138.455)
  line L8 (-188.0031, 150.455) -> (-188.0031, 138.455)
  line L9 (-205.0031, 150.455) -> (-188.0031, 150.455)
  line L10 (-205.0031, 138.455) -> (-205.0031, 150.455)
  line L11 (-222.0031, 138.455) -> (-205.0031, 138.455)
  line L12 (-222.0031, 0) -> (-222.0031, 138.455)
  line L13 (-210.3961, 143.848) -> (-205.0031, 138.455)
  line L14 (-197.3762, 138.455) -> (-205.0031, 138.455)
  line L15 (-180.8799, 145.5782) -> (-188.0031, 138.455)
  line L16 (-177.9293, 138.455) -> (-188.0031, 138.455)
  line L17 (-182.4256, 149.8775) -> (-171.0031, 138.455)
  line L18 (-154.8492, 138.455) -> (-171.0031, 138.455)
  line L19 (-147.3277, 145.1304) -> (-154.0031, 138.455)
  line L20 (-144.5627, 138.455) -> (-154.0031, 138.455)
  circle C1 centre (-196.5031, 144.455) radius 1.5
  circle C2 centre (-162.5031, 144.455) radius 1.5
  circle C3 centre (-151.8464, 140.6117) radius 3.05
  circle C4 centre (-173.1597, 140.6117) radius 3.05
  circle C5 centre (-185.8464, 140.6117) radius 3.05
  circle C6 centre (-207.1597, 140.6117) radius 3.05
  point P14 (-205.0031, 138.455)
  point P16 (-205.0031, 138.455)
  point P11 (-188.0031, 138.455)
  point P19 (-188.0031, 138.455)
  point P10 (-171.0031, 138.455)
  point P22 (-171.0031, 138.455)
  point P7 (-154.0031, 138.455)
  point P25 (-154.0031, 138.455)
  point P28 (-151.8464, 140.6117)
  point P29 (-173.1597, 140.6117)
  point P30 (-185.8464, 140.6117)
  point P31 (-207.1597, 140.6117)
  horizontal L14
  coincident P14 P16
  horizontal L16
  coincident P11 P19
  horizontal L18
  coincident P10 P22
  horizontal L20
  coincident P7 P25
  coincident L19 P28
  coincident L17 P29
  coincident L15 P30
  coincident L13 P31
  dimension "d481" angle L13 L14 = 135
  dimension "d482" angle L15 L16 = 45
  dimension "d483" angle L17 L18 = 135
  dimension "d484" angle L19 L20 = 45
  dimension "d485" diameter C3 = 6.1
  dimension "d486" diameter C4 = 6.1
  dimension "d487" diameter C5 = 6.1
  dimension "d488" diameter C6 = 6.1
  dimension "d489" distance P16 P31 = 3.05
  dimension "d490" distance P19 P30 = 3.05
  dimension "d491" distance P22 P29 = 3.05
  dimension "d493" distance P25 P28 = 3.05
extrude "Extrusion87" cut sketch "Skizze86" profile of L3 L4 L6 L7 L8 L10 L11 C3 C4 C5 C6 against normal blind 16
chamfer "Fase5" distance 3
sketch "Skizze87" plane through (0, 323.7, 0) normal (0, 1, 0) x axis (-1, 0, 0)
  line L1 (-222.0031, 138.455) -> (-209.3164, 138.455)
  line L2 (-222.0031, 0) -> (-222.0031, 138.455)
  line L3 (-137.0031, 0) -> (-222.0031, 0)
  line L4 (-137.0031, 138.455) -> (-137.0031, 0)
  line L5 (-149.6897, 138.455) -> (-137.0031, 138.455)
  line L6 (-154.0031, 150.455) -> (-154.0031, 142.7684)
  line L7 (-171.0031, 150.455) -> (-154.0031, 150.455)
  line L8 (-171.0031, 142.7684) -> (-171.0031, 150.455)
  line L9 (-183.6897, 138.455) -> (-175.3164, 138.455)
  line L10 (-188.0031, 150.455) -> (-188.0031, 142.7684)
  line L11 (-205.0031, 150.455) -> (-188.0031, 150.455)
  line L12 (-205.0031, 142.7684) -> (-205.0031, 150.455)
  line L13 (-222.0031, 12) -> (-205.0031, 12)
  line L14 (-222.0031, 0) -> (-222.0031, 12)
  line L15 (-205.0031, 0) -> (-222.0031, 0)
  line L16 (-205.0031, 12) -> (-205.0031, 0)
  line L17 (-188.0031, 12) -> (-171.0031, 12)
  line L18 (-188.0031, 0) -> (-188.0031, 12)
  line L19 (-171.0031, 0) -> (-188.0031, 0)
  line L20 (-171.0031, 12) -> (-171.0031, 0)
  line L21 (-154.0031, 12) -> (-137.0031, 12)
  line L22 (-154.0031, 0) -> (-154.0031, 12)
  line L23 (-137.0031, 0) -> (-154.0031, 0)
  line L24 (-137.0031, 12) -> (-137.0031, 0)
  circle C1 centre (-196.5031, 144.455) radius 4.5
  arc A1 centre (-207.1597, 140.6117) radius 3.05 clockwise from (-205.0031, 142.7684) to (-209.3164, 138.455)
  arc A2 centre (-151.8464, 140.6117) radius 3.05 clockwise from (-149.6897, 138.455) to (-154.0031, 142.7684)
  arc A3 centre (-173.1597, 140.6117) radius 3.05 clockwise from (-171.0031, 142.7684) to (-175.3164, 138.455)
  arc A4 centre (-185.8464, 140.6117) radius 3.05 clockwise from (-183.6897, 138.455) to (-188.0031, 142.7684)
  circle C2 centre (-162.5031, 144.455) radius 4.5
extrude "Extrusion88" cut sketch "Skizze87" profile of L2 L3 L4 L13 L14 L15 L16 L17 L18 L19 L20 L21 L22 L23 L24 against normal blind 30
sketch "Skizze88" plane through (0, 323.7, 0) normal (0, 1, 0) x axis (-1, 0, 0)
  line L1 (-205.0031, 0) -> (-205.0031, 12)
  line L2 (-188.0031, 0) -> (-205.0031, 0)
  line L3 (-188.0031, 12) -> (-188.0031, 0)
  line L4 (-171.0031, 12) -> (-188.0031, 12)
  line L5 (-171.0031, 0) -> (-171.0031, 12)
  line L6 (-154.0031, 0) -> (-171.0031, 0)
  line L7 (-154.0031, 12) -> (-154.0031, 0)
  line L8 (-137.0031, 12) -> (-154.0031, 12)
  line L9 (-137.0031, 138.455) -> (-137.0031, 12)
  line L10 (-149.6897, 138.455) -> (-137.0031, 138.455)
  line L11 (-154.0031, 150.455) -> (-154.0031, 142.7684)
  line L12 (-171.0031, 150.455) -> (-154.0031, 150.455)
  line L13 (-171.0031, 142.7684) -> (-171.0031, 150.455)
  line L14 (-183.6897, 138.455) -> (-175.3164, 138.455)
  line L15 (-188.0031, 150.455) -> (-188.0031, 142.7684)
  line L16 (-205.0031, 150.455) -> (-188.0031, 150.455)
  line L17 (-205.0031, 142.7684) -> (-205.0031, 150.455)
  line L18 (-222.0031, 138.455) -> (-209.3164, 138.455)
  line L19 (-222.0031, 12) -> (-222.0031, 138.455)
  line L20 (-205.0031, 12) -> (-222.0031, 12)
  line L21 (-154.0031, 12) -> (-205.0031, 12)
  line L22 (-154.0031, 0) -> (-171.0031, 12)
  line L23 (-171.0031, 0) -> (-154.0031, 12)
  line L24 (-188.0031, 0) -> (-205.0031, 12)
  line L25 (-205.0031, 0) -> (-188.0031, 12)
  arc A1 centre (-151.8464, 140.6117) radius 3.05 clockwise from (-149.6897, 138.455) to (-154.0031, 142.7684)
  arc A2 centre (-173.1597, 140.6117) radius 3.05 clockwise from (-171.0031, 142.7684) to (-175.3164, 138.455)
  arc A3 centre (-185.8464, 140.6117) radius 3.05 clockwise from (-183.6897, 138.455) to (-188.0031, 142.7684)
  arc A4 centre (-207.1597, 140.6117) radius 3.05 clockwise from (-205.0031, 142.7684) to (-209.3164, 138.455)
  circle C1 centre (-196.5031, 144.455) radius 4.5
  circle C2 centre (-162.5031, 144.455) radius 4.5
  circle C3 centre (-196.5031, 6) radius 1.5
  circle C4 centre (-162.5031, 6) radius 1.5
  point P2 (-205.0031, 12)
  point P32 (-205.0031, 12)
  point P9 (-154.0031, 12)
  point P33 (-154.0031, 12)
  point P6 (-171.0031, 12)
  point P34 (-171.0031, 12)
  point P8 (-154.0031, 0)
  point P35 (-154.0031, 0)
  point P7 (-171.0031, 0)
  point P36 (-171.0031, 0)
  point P4 (-188.0031, 0)
  point P37 (-188.0031, 0)
  point P5 (-188.0031, 12)
  point P38 (-188.0031, 12)
  point P3 (-205.0031, 0)
  point P39 (-205.0031, 0)
  point P40 (-196.5031, 6)
  point P41 (-162.5031, 6)
  coincident P2 P32
  coincident P9 P33
  coincident P6 P34
  coincident P8 P35
  coincident P7 P36
  coincident P4 P37
  coincident P5 P38
  coincident P3 P39
  midpoint L25 P40
  midpoint L23 P41
  dimension "d499" diameter C3 = 3
  dimension "d500" diameter C4 = 3
extrude "Extrusion89" cut sketch "Skizze88" profile of C3 C4 against normal blind 51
